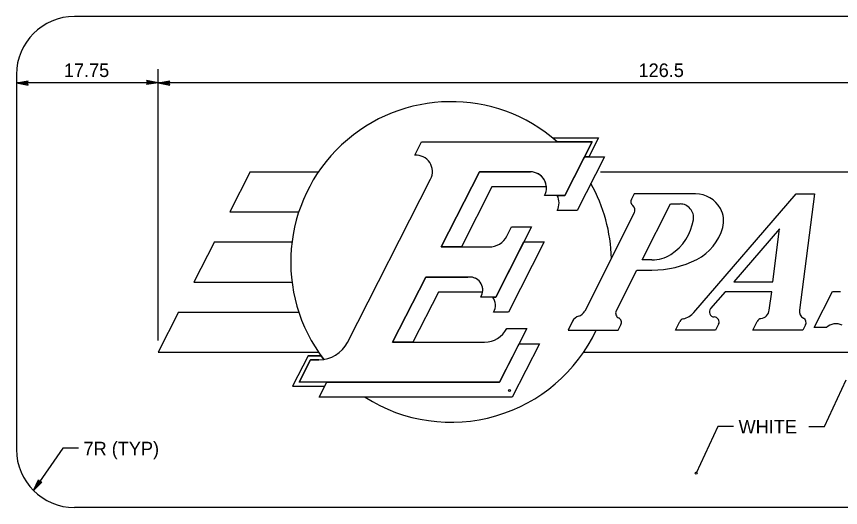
# Model space of a CAD drawing. Extents: x 10268197 to 10268739, y 2141503 to 2142677.
# Drawn here: x 10268669.32 to 10268711.88, y 2142368.9 to 2142394.27 of the extents above; entities that cross this region are included whole.
import ezdxf

# ---------------------------------------------------------------- set-up
doc = ezdxf.new("R2010")
doc.units = 0
for name, color, linetype in [('1', 7, 'Continuous'), ('21', 7, 'Continuous'), ('Default', 7, 'Continuous')]:
    doc.layers.add(name, color=color, linetype=linetype)

msp = doc.modelspace()

# ---------------------------------------------------------------- linework, layer by layer
at = {"layer": '1'}
for p, q in [((10268676.642, 2142377.534), (10268676.642, 2142391.546)), ((10268676.085, 2142390.852), (10268676.036, 2142390.745)), ((10268676.642, 2142390.842), (10268676.036, 2142390.745)), ((10268676.642, 2142390.842), (10268676.04, 2142390.958)), ((10268676.04, 2142390.958), (10268676.085, 2142390.852)), ((10268676.642, 2142390.842), (10268676.062, 2142390.801)), ((10268676.642, 2142390.842), (10268676.064, 2142390.902)), ((10268697.636, 2142385.023), (10268698.652, 2142387.016)), ((10268699.698, 2142387.016), (10268698.287, 2142384.249)), ((10268698.652, 2142387.016), (10268699.698, 2142387.016)), ((10268691.253, 2142382.358), (10268693.231, 2142386.239)), ((10268693.231, 2142386.239), (10268695.869, 2142386.239)), ((10268693.881, 2142385.463), (10268692.299, 2142382.358)), ((10268696.696, 2142385.463), (10268693.881, 2142385.463)), ((10268697.251, 2142385.023), (10268697.636, 2142385.023)), ((10268698.287, 2142384.249), (10268697.252, 2142384.249)), ((10268692.299, 2142382.358), (10268691.253, 2142382.358)), ((10268694.08, 2142379.77), (10268695.531, 2142382.617)), ((10268696.576, 2142382.617), (10268694.73, 2142378.994)), ((10268695.531, 2142382.617), (10268696.576, 2142382.617)), ((10268688.749, 2142377.442), (10268690.463, 2142380.805)), ((10268690.463, 2142380.805), (10268692.636, 2142380.798)), ((10268691.112, 2142380.027), (10268689.794, 2142377.442)), ((10268693.397, 2142380.019), (10268691.112, 2142380.027)), ((10268693.918, 2142379.77), (10268694.08, 2142379.77)), ((10268694.73, 2142378.994), (10268693.954, 2142378.994)), ((10268689.794, 2142377.442), (10268688.749, 2142377.442)), ((10268694.272, 2142375.371), (10268695.286, 2142377.361)), ((10268696.332, 2142377.361), (10268694.922, 2142374.594)), ((10268695.286, 2142377.361), (10268696.332, 2142377.361)), ((10268711.063, 2142373.086), (10268712.178, 2142375.493)), ((10268684.956, 2142374.594), (10268685.352, 2142375.371)), ((10268685.352, 2142375.371), (10268694.272, 2142375.371)), ((10268694.922, 2142374.594), (10268684.956, 2142374.594)), ((10268705.54, 2142373.086), (10268704.425, 2142370.678)), ((10268706.362, 2142373.086), (10268705.54, 2142373.086)), ((10268710.241, 2142373.086), (10268711.063, 2142373.086)), ((10268671.711, 2142371.956), (10268670.201, 2142369.776)), ((10268672.533, 2142371.956), (10268671.711, 2142371.956))]:
    msp.add_line(p, q, dxfattribs=at)
msp.add_lwpolyline([(10268697.01, 2142387.992), (10268699.382, 2142387.992), (10268698.885, 2142387.016), (10268698.652, 2142387.016), (10268699.048, 2142387.792), (10268697.246, 2142387.792)], close=True, dxfattribs=at)
for centre in [(10268694.789, 2142374.949), (10268704.425, 2142370.678)]:
    msp.add_circle(centre, 0.0518, dxfattribs=at)
for centre, radius, start, end in [((10268695.869, 2142385.411), 0.828, 3.5833, 90), ((10268696.519, 2142384.635), 0.828, 332.2089, 27.9127), ((10268692.734, 2142380.133), 0.673, 350.3502, 98.3344), ((10268693.387, 2142379.356), 0.673, 327.421, 37.9799)]:
    msp.add_arc(centre, radius, start, end, dxfattribs=at)
at = {"layer": '21'}
for p, q in [((10268669.322, 2142390.842), (10268669.928, 2142390.938)), ((10268669.322, 2142390.842), (10268669.902, 2142390.882)), ((10268669.322, 2142390.842), (10268669.924, 2142390.725)), ((10268669.322, 2142390.842), (10268669.901, 2142390.781)), ((10268669.88, 2142390.832), (10268669.928, 2142390.938)), ((10268669.924, 2142390.725), (10268669.88, 2142390.832)), ((10268676.642, 2142390.842), (10268677.247, 2142390.938)), ((10268676.642, 2142390.842), (10268677.222, 2142390.882)), ((10268676.642, 2142390.842), (10268677.244, 2142390.725)), ((10268676.642, 2142390.842), (10268677.22, 2142390.781)), ((10268677.2, 2142390.832), (10268677.247, 2142390.938)), ((10268677.244, 2142390.725), (10268677.2, 2142390.832)), ((10268670.201, 2142369.776), (10268670.457, 2142370.332)), ((10268670.201, 2142369.776), (10268670.49, 2142370.28)), ((10268670.519, 2142370.234), (10268670.457, 2142370.332)), ((10268670.201, 2142369.776), (10268670.573, 2142370.223)), ((10268670.201, 2142369.776), (10268670.632, 2142370.211)), ((10268670.632, 2142370.211), (10268670.519, 2142370.234))]:
    msp.add_line(p, q, dxfattribs=at)
at = {"layer": 'Default'}
for p, q in [((10268733.322, 2142394.266), (10268672.322, 2142394.266)), ((10268669.322, 2142391.266), (10268669.322, 2142371.897)), ((10268676.642, 2142390.842), (10268669.322, 2142390.842)), ((10268729.003, 2142390.842), (10268676.642, 2142390.842)), ((10268689.896, 2142387.098), (10268690.249, 2142387.792)), ((10268690.249, 2142387.792), (10268699.048, 2142387.792)), ((10268697.01, 2142387.992), (10268699.382, 2142387.992)), ((10268699.048, 2142387.792), (10268697.638, 2142385.025)), ((10268699.382, 2142387.992), (10268698.885, 2142387.016)), ((10268697.636, 2142385.023), (10268698.652, 2142387.016)), ((10268699.698, 2142387.016), (10268698.287, 2142384.249)), ((10268698.652, 2142387.016), (10268699.698, 2142387.016)), ((10268681.389, 2142386.239), (10268680.334, 2142384.169)), ((10268681.389, 2142386.239), (10268684.922, 2142386.239)), ((10268693.231, 2142386.239), (10268691.253, 2142382.358)), ((10268691.253, 2142382.358), (10268693.231, 2142386.239)), ((10268695.869, 2142386.239), (10268693.231, 2142386.239)), ((10268693.231, 2142386.239), (10268695.869, 2142386.239)), ((10268699.479, 2142386.239), (10268729.003, 2142386.239)), ((10268686.418, 2142377.428), (10268690.713, 2142385.858)), ((10268693.881, 2142385.463), (10268692.299, 2142382.358)), ((10268696.696, 2142385.463), (10268693.881, 2142385.463)), ((10268697.638, 2142385.025), (10268696.602, 2142385.025)), ((10268697.251, 2142385.023), (10268697.636, 2142385.023)), ((10268701.225, 2142385.101), (10268701.084, 2142384.823)), ((10268704.395, 2142385.101), (10268701.225, 2142385.101)), ((10268704.315, 2142378.976), (10268709.6, 2142385.101)), ((10268709.6, 2142385.101), (10268710.532, 2142385.101)), ((10268710.532, 2142385.101), (10268709.757, 2142379.101)), ((10268701.632, 2142381.686), (10268703.096, 2142384.579)), ((10268703.096, 2142384.579), (10268703.595, 2142384.579)), ((10268680.334, 2142384.169), (10268683.903, 2142384.169)), ((10268698.287, 2142384.249), (10268697.252, 2142384.249)), ((10268701.234, 2142384.115), (10268698.672, 2142379.048)), ((10268695.926, 2142383.393), (10268694.08, 2142379.77)), ((10268694.651, 2142382.923), (10268694.891, 2142383.393)), ((10268694.891, 2142383.393), (10268695.926, 2142383.393)), ((10268708.734, 2142383.302), (10268706.371, 2142380.564)), ((10268708.38, 2142380.564), (10268708.734, 2142383.302)), ((10268679.543, 2142382.617), (10268678.488, 2142380.546)), ((10268679.543, 2142382.617), (10268683.553, 2142382.617)), ((10268691.253, 2142382.358), (10268693.73, 2142382.358)), ((10268692.299, 2142382.358), (10268691.253, 2142382.358)), ((10268694.08, 2142379.77), (10268695.531, 2142382.617)), ((10268696.576, 2142382.617), (10268694.73, 2142378.994)), ((10268695.531, 2142382.617), (10268696.576, 2142382.617)), ((10268702.144, 2142381.686), (10268701.632, 2142381.686)), ((10268700.298, 2142379.049), (10268701.368, 2142381.164)), ((10268701.368, 2142381.164), (10268702.144, 2142381.164)), ((10268678.488, 2142380.546), (10268683.553, 2142380.546)), ((10268690.463, 2142380.805), (10268688.749, 2142377.442)), ((10268688.749, 2142377.442), (10268690.463, 2142380.805)), ((10268692.734, 2142380.805), (10268690.463, 2142380.805)), ((10268690.463, 2142380.805), (10268692.636, 2142380.798)), ((10268706.371, 2142380.564), (10268708.38, 2142380.564)), ((10268691.112, 2142380.027), (10268689.794, 2142377.442)), ((10268693.397, 2142380.019), (10268691.112, 2142380.027)), ((10268694.08, 2142379.77), (10268693.301, 2142379.77)), ((10268693.918, 2142379.77), (10268694.08, 2142379.77)), ((10268705.923, 2142380.043), (10268705.172, 2142379.174)), ((10268708.328, 2142380.043), (10268705.923, 2142380.043)), ((10268708.205, 2142379.101), (10268708.328, 2142380.043)), ((10268710.528, 2142378.193), (10268711.468, 2142380.051)), ((10268711.468, 2142380.051), (10268711.883, 2142380.051)), ((10268677.697, 2142378.994), (10268676.642, 2142376.923)), ((10268677.697, 2142378.994), (10268683.903, 2142378.994)), ((10268694.73, 2142378.994), (10268693.954, 2142378.994)), ((10268698.042, 2142378.522), (10268697.81, 2142378.062)), ((10268703.363, 2142378.062), (10268703.588, 2142378.508)), ((10268707.357, 2142378.062), (10268707.585, 2142378.514)), ((10268695.682, 2142378.138), (10268694.272, 2142375.371)), ((10268694.646, 2142378.138), (10268695.682, 2142378.138)), ((10268697.81, 2142378.062), (10268700.397, 2142378.062)), ((10268700.397, 2142378.062), (10268700.539, 2142378.341)), ((10268705.433, 2142378.062), (10268703.363, 2142378.062)), ((10268705.586, 2142378.363), (10268705.433, 2142378.062)), ((10268709.945, 2142378.062), (10268707.357, 2142378.062)), ((10268710.081, 2142378.331), (10268709.945, 2142378.062)), ((10268711.157, 2142378.193), (10268710.528, 2142378.193)), ((10268688.749, 2142377.442), (10268693.498, 2142377.442)), ((10268689.794, 2142377.442), (10268688.749, 2142377.442)), ((10268694.272, 2142375.371), (10268695.286, 2142377.361)), ((10268696.332, 2142377.361), (10268694.922, 2142374.594)), ((10268695.286, 2142377.361), (10268696.332, 2142377.361)), ((10268676.642, 2142376.923), (10268684.922, 2142376.923)), ((10268684.381, 2142376.731), (10268683.583, 2142375.163)), ((10268684.381, 2142376.731), (10268685.057, 2142376.731)), ((10268698.615, 2142376.923), (10268724.257, 2142376.923)), ((10268683.921, 2142375.371), (10268684.508, 2142376.524)), ((10268684.508, 2142376.524), (10268683.922, 2142375.371)), ((10268684.508, 2142376.524), (10268684.943, 2142376.524)), ((10268684.943, 2142376.524), (10268684.508, 2142376.524)), ((10268683.583, 2142375.163), (10268685.246, 2142375.163)), ((10268694.272, 2142375.371), (10268683.921, 2142375.371)), ((10268684.956, 2142374.594), (10268685.352, 2142375.371)), ((10268685.352, 2142375.371), (10268694.272, 2142375.371)), ((10268694.922, 2142374.594), (10268684.956, 2142374.594)), ((10268733.322, 2142368.897), (10268672.322, 2142368.897))]:
    msp.add_line(p, q, dxfattribs=at)
msp.add_lwpolyline([(10268685.057, 2142376.731), (10268684.381, 2142376.731), (10268683.583, 2142375.163), (10268685.246, 2142375.163), (10268685.352, 2142375.371), (10268683.921, 2142375.371), (10268684.508, 2142376.524), (10268684.943, 2142376.524), (10268685.197, 2142376.544)], close=True, dxfattribs=at)
for centre, radius, start, end in [((10268672.322, 2142391.266), 3, 90, 180), ((10268691.769, 2142381.582), 8.281, 48.5904, 217.4725), ((10268689.953, 2142386.246), 0.854, 332.9998, 93.8045), ((10268695.869, 2142385.411), 0.828, 332.2089, 90), ((10268695.869, 2142385.411), 0.828, 3.5833, 90), ((10268691.769, 2142381.582), 8.281, 1.2967, 29.2778), ((10268696.519, 2142384.635), 0.828, 332.2089, 27.9127), ((10268693.729, 2142383.393), 1.035, 270, 332.9883), ((10268692.734, 2142380.133), 0.673, 350.3502, 98.3344), ((10268692.734, 2142380.133), 0.673, 327.421, 90), ((10268693.387, 2142379.356), 0.673, 327.421, 37.9799), ((10268691.769, 2142381.582), 8.281, 237.5383, 334.8493), ((10268693.498, 2142378.735), 1.294, 270, 332.5096), ((10268684.943, 2142378.18), 1.656, 270, 332.9991), ((10268672.322, 2142371.897), 3, 180, 270)]:
    msp.add_arc(centre, radius, start, end, dxfattribs=at)
for centre, major_axis, start_param, end_param in [((10268701.315, 2142384.704), (0, -0.261), 4.240773, 5.605302), ((10268704.395, 2142383.615), (0, 1.486), 5.226065, 6.283185), ((10268700.958, 2142384.258), (0, -0.313), 1.099604, 2.46371), ((10268703.594, 2142383.876), (0, -0.704), 1.415043, 3.141593), ((10268704.553, 2142383.705), (0, 1.303), 4.445482, 5.226065), ((10268701.728, 2142384.171), (0, -2.607), 0.565847, 1.415043), ((10268703.304, 2142384.048), (0, -2.607), 0.465011, 1.30389), ((10268702.144, 2142383.511), (0, -1.825), 0, 0.565847), ((10268702.144, 2142386.378), (0, -5.214), 0, 0.465011), ((10268698.211, 2142379.285), (0, -0.521), 0.286787, 1.099486), ((10268700.528, 2142378.931), (0, 0.261), 1.099355, 2.701477), ((10268703.534, 2142379.661), (0, -1.043), 0.22194, 0.855152), ((10268705.367, 2142379.003), (0, 0.261), 0.854904, 3.118676), ((10268707.692, 2142379.168), (0, -0.521), 0.161263, 1.440999), ((10268710.168, 2142379.047), (0, 0.417), 1.441439, 2.650585), ((10268698.504, 2142378.285), (0, -0.521), 3.428379, 4.240701), ((10268700.308, 2142378.459), (0, 0.261), 4.241567, 5.84307), ((10268703.819, 2142378.39), (0, -0.261), 3.363532, 4.241567), ((10268705.355, 2142378.482), (0, 0.261), 4.240773, 6.260268), ((10268707.816, 2142378.396), (0, -0.261), 3.302856, 4.241567), ((10268709.85, 2142378.449), (0, 0.261), 4.240773, 5.792177), ((10268711.653, 2142377.66), (0, -0.73), 2.69443, 3.895387)]:
    msp.add_ellipse(centre, major_axis=major_axis, ratio=0.992614, start_param=start_param, end_param=end_param, dxfattribs=at)

# ---------------------------------------------------------------- texts
at = {"layer": '1'}
for s, p in [('17.75', (10268671.77, 2142391.137)), ('126.5', (10268701.451, 2142391.137)), ('WHITE', (10268706.618, 2142372.723)), ('7R (TYP)', (10268672.786, 2142371.593))]:
    msp.add_text(s, height=0.7, dxfattribs=at).set_placement(p)

doc.saveas('drawing.dxf')
